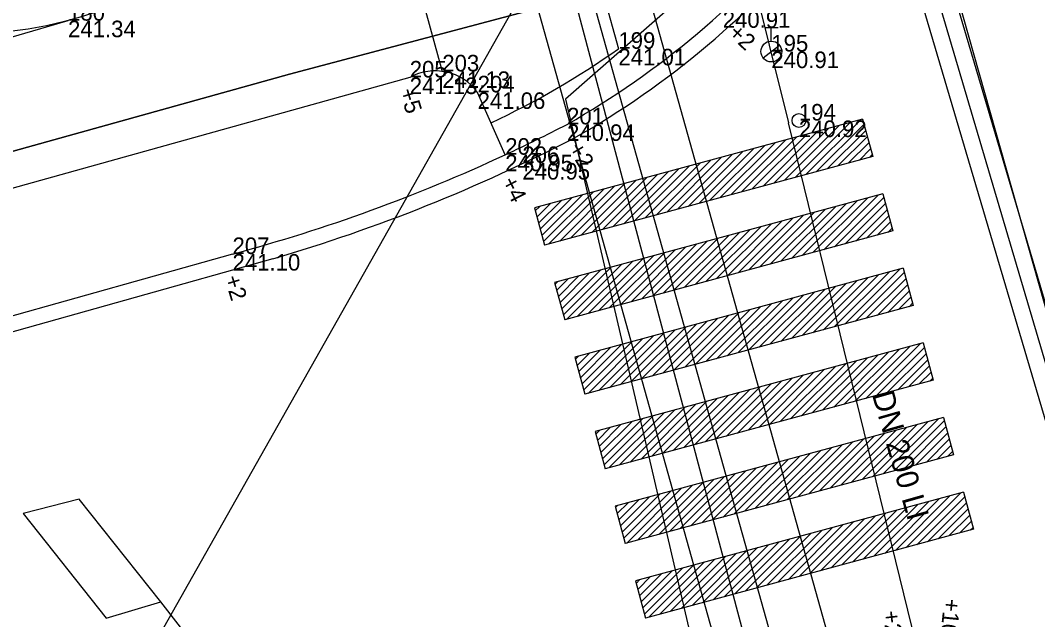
# Model space of a CAD drawing. Extents: x -599432 to -598680, y -1159407 to -1158632.
# Drawn here: x -599047.81 to -599029.38, y -1158908.71 to -1158897.84 of the extents above; entities that cross this region are included whole.
import ezdxf

# ---------------------------------------------------------------- set-up
doc = ezdxf.new("R2010")
doc.units = 0
for name, color, linetype in [('0004 VY - Body podrobné', 7, 'Continuous'), ('0005 VY - Body podrobné - čísla', 7, 'Continuous'), ('0006 VY - Body podrobné - výšky', 7, 'Continuous'), ('0027 ZA - Silnice_cesta zpevněná', 7, 'Continuous'), ('0028 ZA - Silnice - nájezd na chodník', 7, 'Continuous'), ('0030 ZA - Chodník', 7, 'Continuous'), ('0031 ZA - Ostatní rozhraní', 7, 'Continuous'), ('0063 ZA - Doprava - vodorovné značení', 7, 'Continuous'), ('0073 TE - Výška obrubníků a zdí', 7, 'Continuous'), ('0080 ZA - BVK - vodovod - buňky', 7, 'Continuous'), ('0206 PV - BVK - kanalizace - jednotná', 7, 'Continuous'), ('0213 PV - BVK - vodovod - popis', 7, 'Continuous'), ('0214 PV - BVK - vodovod - pitná', 7, 'Continuous'), ('0264 PV - TB - parovod mimo provoz', 7, 'Continuous'), ('0302 PV - RWE - NTL', 7, 'Continuous'), ('0308 PV - RWE - ochranné pásmo', 7, 'Continuous'), ('0407 PV - TSB - kabelové vedení přibližný zákres', 7, 'Continuous'), ('0455 PV - O2 - kabel nezaměřený', 7, 'Continuous'), ('0652 PV - BKOM - kabely bez rozlišení', 7, 'Continuous'), ('0653 PV - BKOM - chranička', 7, 'Continuous')]:
    doc.layers.add(name, color=color, linetype=linetype)

msp = doc.modelspace()

# ---------------------------------------------------------------- linework, layer by layer
at = {"layer": '0004 VY - Body podrobné'}
for p, q in [((-599046.95, -1158897.85), (-599046.95, -1158897.85)), ((-599036.98, -1158898.36), (-599036.98, -1158898.36)), ((-599034.21, -1158898.41), (-599034.21, -1158898.41)), ((-599040.76, -1158898.88), (-599040.76, -1158898.88)), ((-599040.17, -1158898.77), (-599040.17, -1158898.77)), ((-599039.53, -1158899.15), (-599039.53, -1158899.15)), ((-599037.91, -1158899.73), (-599037.91, -1158899.73)), ((-599033.71, -1158899.66), (-599033.71, -1158899.66)), ((-599039.03, -1158900.28), (-599039.03, -1158900.28)), ((-599038.72, -1158900.43), (-599038.72, -1158900.43)), ((-599043.97, -1158902.08), (-599043.97, -1158902.08))]:
    msp.add_line(p, q, dxfattribs=at)
at = {"layer": '0027 ZA - Silnice_cesta zpevněná'}
for p, q in [((-599040.76, -1158898.88), (-599061.79, -1158904.74)), ((-599039.03, -1158900.28), (-599039.53, -1158899.15))]:
    msp.add_line(p, q, dxfattribs=at)
for centre, radius, start, end in [((-599045.614, -1158886.167), 15.598, 299.5987, 320.7801), ((-599040.299, -1158899.716), 0.955, 36.3585, 118.88), ((-599051.873, -1158872.711), 30.414, 294.9789, 297.3297)]:
    msp.add_arc(centre, radius, start, end, dxfattribs=at)
at = {"layer": '0028 ZA - Silnice - nájezd na chodník'}
msp.add_line((-599043.97, -1158902.08), (-599060.19, -1158906.64), dxfattribs=at)
msp.add_arc((-599051.873, -1158872.711), 30.414, 285.0617, 294.9789, dxfattribs=at)
at = {"layer": '0030 ZA - Chodník'}
msp.add_circle((-599048.702, -1158891.314), 6.767, dxfattribs=at)
at = {"layer": '0031 ZA - Ostatní rozhraní'}
for p, q in [((-599041.14, -1158883.437), (-599036.98, -1158898.36)), ((-599041.992, -1158892.187), (-599040.17, -1158898.77)), ((-599063.78, -1158902.71), (-599046.95, -1158897.85)), ((-599043.238, -1158902.165), (-599062.124, -1158907.474))]:
    msp.add_line(p, q, dxfattribs=at)
for centre, radius, start, end in [((-599045.614, -1158886.167), 15.878, 299.5786, 320.8043), ((-599045.614, -1158886.167), 14.94, 295.0598, 305.3043), ((-599051.873, -1158872.711), 30.694, 286.3403, 297.34)]:
    msp.add_arc(centre, radius, start, end, dxfattribs=at)
at = {"layer": '0063 ZA - Doprava - vodorovné značení'}
for p, q in [((-599032.555, -1158899.635), (-599038.5, -1158901.243)), ((-599034.166, -1158900.796), (-599033.172, -1158899.802)), ((-599033.972, -1158900.744), (-599032.978, -1158899.75)), ((-599033.778, -1158900.691), (-599032.784, -1158899.697)), ((-599033.584, -1158900.639), (-599032.59, -1158899.645)), ((-599033.39, -1158900.586), (-599032.53, -1158899.726)), ((-599032.555, -1158899.635), (-599032.372, -1158900.311)), ((-599034.747, -1158900.953), (-599033.753, -1158899.959)), ((-599034.554, -1158900.901), (-599033.56, -1158899.907)), ((-599034.36, -1158900.849), (-599033.366, -1158899.855)), ((-599033.197, -1158900.534), (-599032.5, -1158899.838)), ((-599033.003, -1158900.482), (-599032.47, -1158899.949)), ((-599035.523, -1158901.163), (-599034.529, -1158900.169)), ((-599035.329, -1158901.111), (-599034.335, -1158900.117)), ((-599035.135, -1158901.058), (-599034.141, -1158900.064)), ((-599034.941, -1158901.006), (-599033.947, -1158900.012)), ((-599032.809, -1158900.429), (-599032.44, -1158900.06)), ((-599032.615, -1158900.377), (-599032.41, -1158900.172)), ((-599032.372, -1158900.311), (-599038.317, -1158901.919)), ((-599036.104, -1158901.32), (-599035.11, -1158900.326)), ((-599035.911, -1158901.268), (-599034.917, -1158900.274)), ((-599035.717, -1158901.216), (-599034.723, -1158900.222)), ((-599032.421, -1158900.324), (-599032.38, -1158900.283)), ((-599036.88, -1158901.53), (-599035.886, -1158900.536)), ((-599036.686, -1158901.478), (-599035.692, -1158900.484)), ((-599036.492, -1158901.425), (-599035.498, -1158900.431)), ((-599036.298, -1158901.373), (-599035.304, -1158900.379)), ((-599037.461, -1158901.687), (-599036.467, -1158900.693)), ((-599037.267, -1158901.635), (-599036.273, -1158900.641)), ((-599037.074, -1158901.583), (-599036.08, -1158900.589)), ((-599038.237, -1158901.897), (-599037.243, -1158900.903)), ((-599038.043, -1158901.845), (-599037.049, -1158900.851)), ((-599037.849, -1158901.792), (-599036.855, -1158900.798)), ((-599037.655, -1158901.74), (-599036.661, -1158900.746)), ((-599038.395, -1158901.631), (-599037.824, -1158901.06)), ((-599038.365, -1158901.743), (-599037.63, -1158901.008)), ((-599038.335, -1158901.854), (-599037.437, -1158900.956)), ((-599032.189, -1158900.987), (-599038.135, -1158902.595)), ((-599033.455, -1158902.054), (-599032.461, -1158901.06)), ((-599033.261, -1158902.002), (-599032.267, -1158901.008)), ((-599033.067, -1158901.949), (-599032.171, -1158901.053)), ((-599032.189, -1158900.987), (-599032.007, -1158901.662)), ((-599038.5, -1158901.243), (-599038.317, -1158901.919)), ((-599038.485, -1158901.297), (-599038.406, -1158901.218)), ((-599038.455, -1158901.409), (-599038.212, -1158901.165)), ((-599038.425, -1158901.52), (-599038.018, -1158901.113)), ((-599034.23, -1158902.264), (-599033.236, -1158901.27)), ((-599034.037, -1158902.211), (-599033.043, -1158901.217)), ((-599033.843, -1158902.159), (-599032.849, -1158901.165)), ((-599033.649, -1158902.107), (-599032.655, -1158901.113)), ((-599032.873, -1158901.897), (-599032.141, -1158901.165)), ((-599032.68, -1158901.844), (-599032.111, -1158901.276)), ((-599034.812, -1158902.421), (-599033.818, -1158901.427)), ((-599034.618, -1158902.369), (-599033.624, -1158901.375)), ((-599034.424, -1158902.316), (-599033.43, -1158901.322)), ((-599032.486, -1158901.792), (-599032.081, -1158901.387)), ((-599035.587, -1158902.631), (-599034.593, -1158901.637)), ((-599035.393, -1158902.578), (-599034.399, -1158901.584)), ((-599035.2, -1158902.526), (-599034.206, -1158901.532)), ((-599035.006, -1158902.474), (-599034.012, -1158901.48)), ((-599032.292, -1158901.74), (-599032.051, -1158901.499)), ((-599032.098, -1158901.687), (-599032.021, -1158901.61)), ((-599032.007, -1158901.662), (-599037.952, -1158903.27)), ((-599036.169, -1158902.788), (-599035.175, -1158901.794)), ((-599035.975, -1158902.736), (-599034.981, -1158901.742)), ((-599035.781, -1158902.683), (-599034.787, -1158901.689)), ((-599036.944, -1158902.998), (-599035.95, -1158902.004)), ((-599036.75, -1158902.945), (-599035.756, -1158901.952)), ((-599036.557, -1158902.893), (-599035.563, -1158901.899)), ((-599036.363, -1158902.841), (-599035.369, -1158901.847)), ((-599037.526, -1158903.155), (-599036.532, -1158902.161)), ((-599037.332, -1158903.103), (-599036.338, -1158902.109)), ((-599037.138, -1158903.05), (-599036.144, -1158902.056)), ((-599038.006, -1158903.07), (-599037.307, -1158902.371)), ((-599037.976, -1158903.181), (-599037.113, -1158902.319)), ((-599037.914, -1158903.26), (-599036.92, -1158902.266)), ((-599031.824, -1158902.338), (-599037.769, -1158903.946)), ((-599037.72, -1158903.208), (-599036.726, -1158902.214)), ((-599032.877, -1158903.348), (-599031.883, -1158902.354)), ((-599031.824, -1158902.338), (-599031.641, -1158903.014)), ((-599038.096, -1158902.736), (-599037.889, -1158902.528)), ((-599038.066, -1158902.847), (-599037.695, -1158902.476)), ((-599038.036, -1158902.958), (-599037.501, -1158902.423)), ((-599033.652, -1158903.558), (-599032.658, -1158902.564)), ((-599033.458, -1158903.505), (-599032.464, -1158902.511)), ((-599033.265, -1158903.453), (-599032.271, -1158902.459)), ((-599033.071, -1158903.401), (-599032.077, -1158902.407)), ((-599032.683, -1158903.296), (-599031.803, -1158902.416)), ((-599032.489, -1158903.243), (-599031.773, -1158902.527)), ((-599038.135, -1158902.595), (-599037.952, -1158903.27)), ((-599038.126, -1158902.624), (-599038.083, -1158902.581)), ((-599034.234, -1158903.715), (-599033.24, -1158902.721)), ((-599034.04, -1158903.663), (-599033.046, -1158902.669)), ((-599033.846, -1158903.61), (-599032.852, -1158902.616)), ((-599032.295, -1158903.191), (-599031.743, -1158902.638)), ((-599032.101, -1158903.138), (-599031.713, -1158902.75)), ((-599035.009, -1158903.925), (-599034.015, -1158902.931)), ((-599034.815, -1158903.872), (-599033.821, -1158902.878)), ((-599034.621, -1158903.82), (-599033.627, -1158902.826)), ((-599034.428, -1158903.768), (-599033.434, -1158902.774)), ((-599031.908, -1158903.086), (-599031.682, -1158902.861)), ((-599031.641, -1158903.014), (-599037.586, -1158904.622)), ((-599035.591, -1158904.082), (-599034.597, -1158903.088)), ((-599035.397, -1158904.03), (-599034.403, -1158903.036)), ((-599035.203, -1158903.977), (-599034.209, -1158902.983)), ((-599031.714, -1158903.034), (-599031.652, -1158902.972)), ((-599036.366, -1158904.292), (-599035.372, -1158903.298)), ((-599036.172, -1158904.239), (-599035.178, -1158903.245)), ((-599035.978, -1158904.187), (-599034.984, -1158903.193)), ((-599035.785, -1158904.135), (-599034.791, -1158903.141)), ((-599036.948, -1158904.449), (-599035.954, -1158903.455)), ((-599036.754, -1158904.397), (-599035.76, -1158903.403)), ((-599036.56, -1158904.344), (-599035.566, -1158903.35)), ((-599037.607, -1158904.543), (-599036.729, -1158903.665)), ((-599037.529, -1158904.606), (-599036.535, -1158903.612)), ((-599037.335, -1158904.554), (-599036.341, -1158903.56)), ((-599037.142, -1158904.502), (-599036.148, -1158903.508)), ((-599037.698, -1158904.209), (-599037.311, -1158903.822)), ((-599037.668, -1158904.321), (-599037.117, -1158903.77)), ((-599037.638, -1158904.432), (-599036.923, -1158903.717)), ((-599031.458, -1158903.69), (-599037.403, -1158905.298)), ((-599033.08, -1158904.853), (-599032.086, -1158903.859)), ((-599032.887, -1158904.801), (-599031.893, -1158903.807)), ((-599032.693, -1158904.749), (-599031.699, -1158903.755)), ((-599032.499, -1158904.696), (-599031.505, -1158903.702)), ((-599032.305, -1158904.644), (-599031.435, -1158903.774)), ((-599031.458, -1158903.69), (-599031.276, -1158904.365)), ((-599037.769, -1158903.946), (-599037.586, -1158904.622)), ((-599037.758, -1158903.987), (-599037.698, -1158903.927)), ((-599037.728, -1158904.098), (-599037.505, -1158903.875)), ((-599033.662, -1158905.011), (-599032.668, -1158904.017)), ((-599033.468, -1158904.958), (-599032.474, -1158903.964)), ((-599033.274, -1158904.906), (-599032.28, -1158903.912)), ((-599032.111, -1158904.591), (-599031.405, -1158903.886)), ((-599031.917, -1158904.539), (-599031.375, -1158903.997)), ((-599034.437, -1158905.221), (-599033.443, -1158904.227)), ((-599034.244, -1158905.168), (-599033.25, -1158904.174)), ((-599034.05, -1158905.116), (-599033.056, -1158904.122)), ((-599033.856, -1158905.063), (-599032.862, -1158904.069)), ((-599031.723, -1158904.486), (-599031.345, -1158904.108)), ((-599031.53, -1158904.434), (-599031.315, -1158904.219)), ((-599031.276, -1158904.365), (-599037.221, -1158905.973)), ((-599035.019, -1158905.378), (-599034.025, -1158904.384)), ((-599034.825, -1158905.325), (-599033.831, -1158904.331)), ((-599034.631, -1158905.273), (-599033.637, -1158904.279)), ((-599031.336, -1158904.382), (-599031.285, -1158904.331)), ((-599035.794, -1158905.588), (-599034.8, -1158904.594)), ((-599035.601, -1158905.535), (-599034.607, -1158904.541)), ((-599035.407, -1158905.483), (-599034.413, -1158904.489)), ((-599035.213, -1158905.43), (-599034.219, -1158904.436)), ((-599036.376, -1158905.745), (-599035.382, -1158904.751)), ((-599036.182, -1158905.692), (-599035.188, -1158904.698)), ((-599035.988, -1158905.64), (-599034.994, -1158904.646)), ((-599037.151, -1158905.955), (-599036.157, -1158904.961)), ((-599036.957, -1158905.902), (-599035.963, -1158904.908)), ((-599036.764, -1158905.85), (-599035.77, -1158904.856)), ((-599036.57, -1158905.797), (-599035.576, -1158904.803)), ((-599037.3, -1158905.679), (-599036.739, -1158905.118)), ((-599037.27, -1158905.791), (-599036.545, -1158905.065)), ((-599037.24, -1158905.902), (-599036.351, -1158905.013)), ((-599031.093, -1158905.041), (-599037.038, -1158906.649)), ((-599032.37, -1158906.112), (-599031.376, -1158905.118)), ((-599032.176, -1158906.059), (-599031.182, -1158905.065)), ((-599031.982, -1158906.007), (-599031.077, -1158905.101)), ((-599031.093, -1158905.041), (-599030.91, -1158905.717)), ((-599037.403, -1158905.298), (-599037.221, -1158905.973)), ((-599037.391, -1158905.345), (-599037.32, -1158905.275)), ((-599037.36, -1158905.457), (-599037.127, -1158905.223)), ((-599037.33, -1158905.568), (-599036.933, -1158905.17)), ((-599033.145, -1158906.321), (-599032.151, -1158905.327)), ((-599032.951, -1158906.269), (-599031.957, -1158905.275)), ((-599032.757, -1158906.216), (-599031.763, -1158905.222)), ((-599032.563, -1158906.164), (-599031.569, -1158905.17)), ((-599031.788, -1158905.954), (-599031.046, -1158905.213)), ((-599031.594, -1158905.902), (-599031.016, -1158905.324)), ((-599033.727, -1158906.479), (-599032.733, -1158905.485)), ((-599033.533, -1158906.426), (-599032.539, -1158905.432)), ((-599033.339, -1158906.374), (-599032.345, -1158905.38)), ((-599031.4, -1158905.849), (-599030.986, -1158905.435)), ((-599034.502, -1158906.688), (-599033.508, -1158905.694)), ((-599034.308, -1158906.636), (-599033.314, -1158905.642)), ((-599034.114, -1158906.583), (-599033.12, -1158905.589)), ((-599033.92, -1158906.531), (-599032.926, -1158905.537)), ((-599031.206, -1158905.797), (-599030.956, -1158905.547)), ((-599031.013, -1158905.745), (-599030.926, -1158905.658)), ((-599030.91, -1158905.717), (-599036.855, -1158907.325)), ((-599035.083, -1158906.846), (-599034.089, -1158905.852)), ((-599034.89, -1158906.793), (-599033.896, -1158905.799)), ((-599034.696, -1158906.741), (-599033.702, -1158905.747)), ((-599035.859, -1158907.055), (-599034.865, -1158906.061)), ((-599035.665, -1158907.003), (-599034.671, -1158906.009)), ((-599035.471, -1158906.95), (-599034.477, -1158905.956)), ((-599035.277, -1158906.898), (-599034.283, -1158905.904)), ((-599036.44, -1158907.213), (-599035.446, -1158906.219)), ((-599036.247, -1158907.16), (-599035.253, -1158906.166)), ((-599036.053, -1158907.108), (-599035.059, -1158906.114)), ((-599036.911, -1158907.118), (-599036.222, -1158906.428)), ((-599036.881, -1158907.229), (-599036.028, -1158906.376)), ((-599036.828, -1158907.317), (-599035.834, -1158906.323)), ((-599030.727, -1158906.393), (-599036.672, -1158908)), ((-599036.634, -1158907.265), (-599035.64, -1158906.271)), ((-599031.768, -1158907.399), (-599030.774, -1158906.405)), ((-599030.727, -1158906.393), (-599030.545, -1158907.068)), ((-599037.002, -1158906.784), (-599036.803, -1158906.586)), ((-599036.971, -1158906.895), (-599036.61, -1158906.533)), ((-599036.941, -1158907.006), (-599036.416, -1158906.481)), ((-599032.544, -1158907.609), (-599031.55, -1158906.615)), ((-599032.35, -1158907.556), (-599031.356, -1158906.562)), ((-599032.156, -1158907.504), (-599031.162, -1158906.51)), ((-599031.962, -1158907.452), (-599030.968, -1158906.458)), ((-599031.574, -1158907.347), (-599030.704, -1158906.477)), ((-599031.38, -1158907.294), (-599030.674, -1158906.588)), ((-599037.038, -1158906.649), (-599036.855, -1158907.325)), ((-599037.032, -1158906.672), (-599036.997, -1158906.638)), ((-599033.125, -1158907.766), (-599032.131, -1158906.772)), ((-599032.931, -1158907.714), (-599031.937, -1158906.72)), ((-599032.737, -1158907.661), (-599031.743, -1158906.667)), ((-599031.187, -1158907.242), (-599030.644, -1158906.7)), ((-599030.993, -1158907.189), (-599030.614, -1158906.811)), ((-599033.9, -1158907.976), (-599032.906, -1158906.982)), ((-599033.707, -1158907.923), (-599032.713, -1158906.929)), ((-599033.513, -1158907.871), (-599032.519, -1158906.877)), ((-599033.319, -1158907.819), (-599032.325, -1158906.825)), ((-599030.799, -1158907.137), (-599030.584, -1158906.922)), ((-599030.545, -1158907.068), (-599036.49, -1158908.676)), ((-599034.482, -1158908.133), (-599033.488, -1158907.139)), ((-599034.288, -1158908.081), (-599033.294, -1158907.087)), ((-599034.094, -1158908.028), (-599033.1, -1158907.034)), ((-599030.605, -1158907.085), (-599030.554, -1158907.033)), ((-599035.257, -1158908.343), (-599034.263, -1158907.349)), ((-599035.064, -1158908.29), (-599034.07, -1158907.296)), ((-599034.87, -1158908.238), (-599033.876, -1158907.244)), ((-599034.676, -1158908.186), (-599033.682, -1158907.192)), ((-599035.839, -1158908.5), (-599034.845, -1158907.506)), ((-599035.645, -1158908.448), (-599034.651, -1158907.454)), ((-599035.451, -1158908.395), (-599034.457, -1158907.401)), ((-599036.509, -1158908.605), (-599035.62, -1158907.716)), ((-599036.421, -1158908.657), (-599035.427, -1158907.663)), ((-599036.227, -1158908.605), (-599035.233, -1158907.611)), ((-599036.033, -1158908.553), (-599035.039, -1158907.559)), ((-599036.599, -1158908.271), (-599036.202, -1158907.873)), ((-599036.569, -1158908.382), (-599036.008, -1158907.821)), ((-599036.539, -1158908.493), (-599035.814, -1158907.768)), ((-599036.672, -1158908), (-599036.49, -1158908.676)), ((-599036.66, -1158908.048), (-599036.59, -1158907.978)), ((-599036.629, -1158908.159), (-599036.396, -1158907.926))]:
    msp.add_line(p, q, dxfattribs=at)
at = {"layer": '0080 ZA - BVK - vodovod - buňky'}
for p, q in [((-599034.335, -1158897.972), (-599034.085, -1158897.972)), ((-599034.21, -1158898.222), (-599034.21, -1158897.972)), ((-599034.357, -1158898.526), (-599034.062, -1158898.294))]:
    msp.add_line(p, q, dxfattribs=at)
for centre, radius in [((-599034.21, -1158898.41), 0.188), ((-599033.71, -1158899.66), 0.125)]:
    msp.add_circle(centre, radius, dxfattribs=at)
at = {"layer": '0206 PV - BVK - kanalizace - jednotná'}
msp.add_line((-599055.379, -1158926.835), (-599034.71, -1158890.253), dxfattribs=at)
msp.add_line((-599055.379, -1158926.835), (-599034.71, -1158890.253), dxfattribs=at)
at = {"layer": '0214 PV - BVK - vodovod - pitná'}
msp.add_line((-599028.54, -1158921.56), (-599033.898, -1158899.704), dxfattribs=at)
msp.add_lwpolyline([(-599034.512, -1158897.222), (-599034.25, -1158898.295), (-599033.898, -1158899.704)], dxfattribs=at)
at = {"layer": '0264 PV - TB - parovod mimo provoz'}
msp.add_line((-599017.96, -1158942.926), (-599032.913, -1158890.076), dxfattribs=at)
at = {"layer": '0302 PV - RWE - NTL'}
msp.add_lwpolyline([(-599039.81, -1158889.02), (-599019.564, -1158961.355)], dxfattribs=at)
at = {"layer": '0308 PV - RWE - ochranné pásmo'}
msp.add_lwpolyline([(-599018.602, -1158961.079), (-599020.526, -1158961.63), (-599040.773, -1158889.29), (-599040.885, -1158888.891), (-599040.479, -1158888.169), (-599040.08, -1158888.057), (-599039.681, -1158887.945), (-599038.959, -1158888.351), (-599038.847, -1158888.75)], close=True, dxfattribs=at)
at = {"layer": '0407 PV - TSB - kabelové vedení přibližný zákres'}
for p, q in [((-599035.104, -1158896.786), (-599037.938, -1158899.272)), ((-599037.938, -1158899.272), (-599034.212, -1158915.284))]:
    msp.add_line(p, q, dxfattribs=at)
at = {"layer": '0455 PV - O2 - kabel nezaměřený'}
msp.add_lwpolyline([(-599033.5, -1158882.39), (-599041.16, -1158884.69), (-599029.5, -1158928.59)], dxfattribs=at)
at = {"layer": '0652 PV - BKOM - kabely bez rozlišení'}
for points in [[(-599069.54, -1158906.27), (-599056.01, -1158902.46), (-599042.94, -1158898.82), (-599036.88, -1158897.21), (-599035.9, -1158896.65), (-599035.19, -1158895.15), (-599033.43, -1158892.94), (-599032.55, -1158892.85), (-599032.38, -1158891.47), (-599031.43, -1158887.7), (-599033.39, -1158880.98), (-599034.34, -1158877.53), (-599034.11, -1158876.42), (-599020.38, -1158872.59), (-599019.95, -1158872.38), (-599019.48, -1158873.04), (-599018.91, -1158874.17), (-599016.73, -1158875.93), (-599015.62, -1158876.75), (-599013.57, -1158877.37), (-599011.16, -1158877.03), (-599007.55, -1158875.71), (-599006.793, -1158874.464)], [(-599034.11, -1158876.42), (-599034.34, -1158877.53), (-599033.39, -1158880.98), (-599031.43, -1158887.7), (-599032.38, -1158891.47), (-599032.55, -1158892.85), (-599033.43, -1158892.94), (-599035.19, -1158895.15), (-599035.9, -1158896.65), (-599036.88, -1158897.21), (-599042.94, -1158898.82), (-599056.01, -1158902.46), (-599055.88, -1158902.71)], [(-599032.55, -1158892.85), (-599025.77, -1158915.82), (-599025.82, -1158914.68), (-599026.87, -1158913.05), (-599029.47, -1158911.41), (-599032.14, -1158911.02), (-599033.01, -1158911.65), (-599035.81, -1158912.5), (-599040.07, -1158913.21)], [(-599040.07, -1158913.21), (-599040.77, -1158913.04), (-599041.67, -1158913.02), (-599045.27, -1158908.38), (-599046.75, -1158906.52), (-599047.76, -1158906.78), (-599046.26, -1158908.68), (-599045.27, -1158908.38)]]:
    msp.add_lwpolyline(points, dxfattribs=at)
at = {"layer": '0653 PV - BKOM - chranička'}
for p, q in [((-599032.262, -1158892.765), (-599025.482, -1158915.735)), ((-599032.838, -1158892.935), (-599026.058, -1158915.905))]:
    msp.add_line(p, q, dxfattribs=at)

# ---------------------------------------------------------------- texts
at = {"layer": '0005 VY - Body podrobné - čísla'}
for s, p in [('180', (-599046.95, -1158897.85)), ('199', (-599036.98, -1158898.36)), ('195', (-599034.21, -1158898.41)), ('203', (-599040.17, -1158898.77)), ('205', (-599040.76, -1158898.88)), ('204', (-599039.53, -1158899.15)), ('201', (-599037.91, -1158899.73)), ('194', (-599033.71, -1158899.66)), ('202', (-599039.03, -1158900.28)), ('206', (-599038.72, -1158900.43)), ('207', (-599043.97, -1158902.08))]:
    msp.add_text(s, height=0.3, dxfattribs=at).set_placement(p)
at = {"layer": '0006 VY - Body podrobné - výšky'}
for s, p in [('240.91', (-599035.09, -1158897.98)), ('241.34', (-599046.95, -1158898.15)), ('241.01', (-599036.98, -1158898.66)), ('240.91', (-599034.21, -1158898.71)), ('241.13', (-599040.76, -1158899.18)), ('241.13', (-599040.17, -1158899.07)), ('241.06', (-599039.53, -1158899.45)), ('240.94', (-599037.91, -1158900.03)), ('240.92', (-599033.71, -1158899.96)), ('240.95', (-599039.03, -1158900.58)), ('240.95', (-599038.72, -1158900.73)), ('241.10', (-599043.97, -1158902.38))]:
    msp.add_text(s, height=0.3, dxfattribs=at).set_placement(p)
at = {"layer": '0073 TE - Výška obrubníků a zdí'}
for s, rotation, p in [('+2', 317.1477, (-599035.007, -1158898.099)), ('+5', 286.775, (-599040.949, -1158899.122)), ('+2', 300.365, (-599037.896, -1158900.164)), ('+4', 297.134, (-599039.105, -1158900.768)), ('+2', 286.775, (-599044.12, -1158902.511)), ('+10', 264.1656, (-599031.078, -1158908.314)), ('+2', 276.6882, (-599032.188, -1158908.559))]:
    msp.add_text(s, height=0.3, rotation=rotation, dxfattribs=at).set_placement(p)
at = {"layer": '0213 PV - BVK - vodovod - popis'}
msp.add_text('DN 200 LI', height=0.4, rotation=285.9059, dxfattribs=at).set_placement((-599032.39, -1158904.619))

doc.saveas('drawing.dxf')
